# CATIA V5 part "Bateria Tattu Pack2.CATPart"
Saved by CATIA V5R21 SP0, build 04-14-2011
Part number: Bateria Tattu Pack2
Material "DS Red": density 7860 kg/m3, Young's modulus 2e+11 Pa, Poisson ratio 0.266
Bounding box of the stored display mesh (mm): x 173.5 to 386.5, y 42.5 to 111.5, z -48 to 48
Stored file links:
  C:\Users\rodri\OneDrive\Área de Trabalho\FACULDADE\3°semestre\Sistemas Aeroespaciais\Projeto de avião 2019-02\CAD\Bateria Tattu Pack2.CATPart
  C:\Program Files (x86)\Dassault Systemes\B21\intel_a\startup\materials\red_env_512x512.jpg
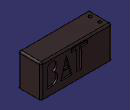
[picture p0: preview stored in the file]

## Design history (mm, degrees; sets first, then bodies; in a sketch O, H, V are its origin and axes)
Body1 (main body), material "DS Red"
  Sketch1 on yz-plane, origin (0, 0, 0), H (0, 1, 0), V (0, 0, 1)
    line L1 (-106.5, 48) -> (106.5, 48)
    line L2 (106.5, 48) -> (106.5, -48)
    line L3 (106.5, -48) -> (-106.5, -48)
    line L4 (-106.5, -48) -> (-106.5, 48)
    distance L4 L2 = 213
    distance L3 L1 = 96
    horizontal: L1 H, L3 H
    vertical: L2 V, L4 V
    symmetry: L4 L2 V, L3 L1 H
  Pad1: profile Sketch1, direction (1, 0, 0), length 34.5, mirrored extent
  Fillet1: radius 5, on edge [face of Pad1 from Sketch1.L1 | face of Pad1 from Sketch1.L2]
  Fillet2: radius 5, on edge [face of Pad1 from Sketch1.L2 | end face of Pad1]; edge [face of Pad1 from Sketch1.L1 | end face of Pad1]; edge [start face of Pad1 | face of Pad1 from Sketch1.L1]; edge [face of Pad1 from Sketch1.L4 | face of Pad1 from Sketch1.L1]; edge [face of Pad1 from Sketch1.L4 | end face of Pad1]; edge [start face of Pad1 | face of Pad1 from Sketch1.L2]
  Fillet3: radius 5, on edge [start face of Pad1 | face of Pad1 from Sketch1.L4]
  Sketch2 on face of Pad1 from Sketch1.L1, origin (0, 0, 48), H (1, 0, 0), V (0, 1, 0)
    circle A1 centre (-14.5, -90) radius 5
    point P1 (-14.5, -90)
    circle A2 centre (14.5, -90) radius 5
    point P2 (14.5, -90)
    reference projected line E1 (-34.5, 101.5) -> (-34.5, -106.5) from edge [start face of Pad1 | face of Fillet2]
    distance P1 E1 = 20
    radius A1 = 5
    radius A2 = 5
    distance A2 H = 85
    symmetry: P1 P2 V
  Pocket1: profile Sketch2, direction (0, 0, -1), length 10
  Sketch3 on start face of Pad1, origin (-34.5, 0, 0), H (0, -1, 0), V (0, 0, 1)
    line L1 (-86.2435, -27.0111) -> (-86.2435, 30.4896)
    arc A1 centre (-73.5977, 21.6671) radius 15.4193 from (-86.2435, 30.4896) to (-68.3938, 7.1525) cw
    arc A2 centre (-74.0974, -9.6616) radius 17.7552 from (-68.3938, 7.1525) to (-70.3235, -27.0111) cw
    line L2 (-70.3235, -27.0111) -> (-86.2435, -27.0111)
    point P7 (-46.9259, -27.0111)
    line L3 (-46.9259, -27.0111) -> (-30.0411, 30.4896)
    line L4 (-30.0411, 30.4896) -> (-13.3975, -27.0111)
    point P9 (-13.3975, -27.0111)
    line L5 (-13.3975, -27.0111) -> (-46.9259, -27.0111)
    point P10 (-37.5187, 0)
    line L6 (-37.5187, 0) -> (-23.046, 0)
    line L7 (-23.046, 0) -> (-23.046, -5.3581)
    line L8 (-23.046, -5.3581) -> (-37.5187, -5.3581)
    line L9 (-37.5187, -5.3581) -> (-37.5187, 0)
    point P14 (0, 30.4896)
    line L10 (0, 30.4896) -> (0, -27.0111)
    point P15 (0, -27.0111)
    line L11 (0, -27.0111) -> (14.58, -26.9312)
    line L12 (14.58, -26.9312) -> (14.2654, 30.4896)
    line L13 (14.2654, 30.4896) -> (32.674, 30.4896)
    line L14 (32.674, 30.4896) -> (32.674, 40.1131)
    line L15 (32.674, 40.1131) -> (-15.086, 40.1131)
    line L16 (-15.086, 40.1131) -> (-15.086, 30.4896)
    point P21 (-15.086, 30.4896)
    line L17 (-15.086, 30.4896) -> (0, 30.4896)
    vertical: L1 V, L7 V, L9 V, L10 V, L14 V, L16 V
    horizontal: L2 H, L5 H, L6 H, L8 H, L13 H, L15 H, L17 H
    coincidence: P7 L2, P9 L2, P10 H, P14 V, P15 L2, P21 L13
    tangency: L11 A2
  Pocket2: profile Sketch3, direction (1, 0, 0), length 5
  Sketch4 on end face of Pad1, origin (34.5, 0, 0), H (0, 1, 0), V (0, 0, 1)
    axis line L1 (-201.212, 0) -> (227.9274, 0)
    point P1 (-201.212, 0)
    coincidence: P1 H
    horizontal: L1 H
  Rotate1: Axis edge [start face of Pad1 | face of Fillet2], Angle 90, ToTransfor Pocket2
  Rotate2: Axis edge [face of Pad1 from Sketch1.L4 | face of Fillet3], Angle 90, ToTransfor Rotate1
  Rotate3: Axis edge [face of Pad1 from Sketch1.L4 | face of Fillet3], Angle 90, ToTransfor Rotate2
